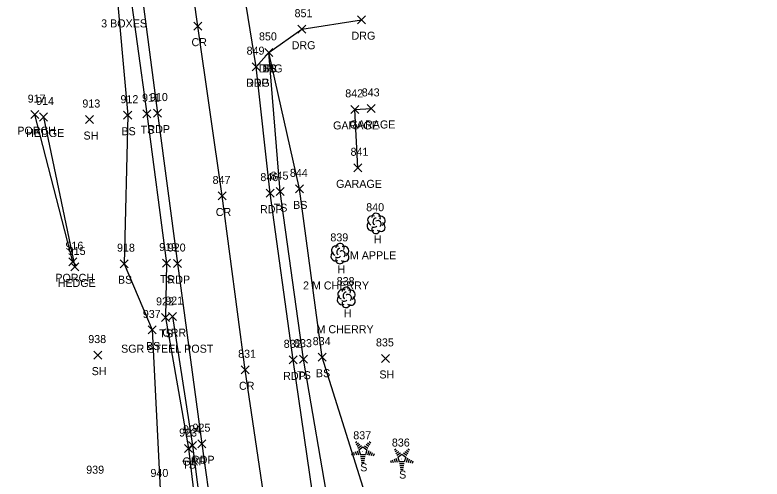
# Model space of a CAD drawing. Extents: x 1629176 to 1637209, y 606063 to 610167.
# Drawn here: x 1629888.9 to 1630075.4, y 607456.1 to 607571.9 of the extents above; entities that cross this region are included whole.
import ezdxf

# ---------------------------------------------------------------- set-up
doc = ezdxf.new("R2010")
doc.units = 0
for name, color, linetype in [('L_A', 7, 'Continuous'), ('L_C', 7, 'Continuous'), ('L_I', 7, 'Continuous'), ('L_TIC', 7, 'Continuous'), ('LAHR', 7, 'Continuous'), ('LBC', 7, 'Continuous'), ('LBF', 7, 'Continuous'), ('LELB', 7, 'Continuous'), ('LTC', 7, 'Continuous'), ('LTD', 7, 'Continuous'), ('P_A', 7, 'Continuous'), ('P_I', 7, 'Continuous'), ('P_TIC', 7, 'Continuous'), ('PET', 7, 'Continuous'), ('PRC', 7, 'Continuous'), ('R_A', 7, 'Continuous'), ('R_C', 7, 'Continuous'), ('R_I', 7, 'Continuous'), ('R_TIC', 7, 'Continuous'), ('RDG', 7, 'Continuous'), ('RGR', 7, 'Continuous')]:
    doc.layers.add(name, color=color, linetype=linetype)

msp = doc.modelspace()

# ---------------------------------------------------------------- linework, layer by layer
at = {"layer": 'L_TIC'}
for points in [[(1629951.27, 607561.54), (1629953.27, 607563.54)], [(1629953.27, 607561.54), (1629951.27, 607563.54)], [(1629951.27, 607561.54), (1629953.27, 607563.54)], [(1629953.27, 607561.54), (1629951.27, 607563.54)], [(1629976.84, 607547.56), (1629978.84, 607549.56)], [(1629978.84, 607547.56), (1629976.84, 607549.56)], [(1629892.84, 607546.01), (1629894.84, 607548.01)], [(1629894.84, 607546.01), (1629892.84, 607548.01)], [(1629916.02, 607545.87), (1629918.02, 607547.87)], [(1629918.02, 607545.87), (1629916.02, 607547.87)], [(1629920.84, 607546.23), (1629922.84, 607548.23)], [(1629922.84, 607546.23), (1629920.84, 607548.23)], [(1629972.72, 607547.32), (1629974.72, 607549.32)], [(1629974.72, 607547.32), (1629972.72, 607549.32)], [(1629894.96, 607545.42), (1629896.96, 607547.42)], [(1629896.96, 607545.42), (1629894.96, 607547.42)], [(1629906.5, 607544.79), (1629908.5, 607546.79)], [(1629908.5, 607544.79), (1629906.5, 607546.79)], [(1629973.47, 607532.74), (1629975.47, 607534.74)], [(1629975.47, 607532.74), (1629973.47, 607534.74)], [(1629958.9, 607527.48), (1629960.9, 607529.48)], [(1629960.9, 607527.48), (1629958.9, 607529.48)], [(1629954.08, 607526.79), (1629956.08, 607528.79)], [(1629956.08, 607526.79), (1629954.08, 607528.79)], [(1629902.34, 607509.29), (1629904.34, 607511.29)], [(1629904.34, 607509.29), (1629902.34, 607511.29)], [(1629915.16, 607508.81), (1629917.16, 607510.81)], [(1629917.16, 607508.81), (1629915.16, 607510.81)], [(1629925.69, 607508.97), (1629927.69, 607510.97)], [(1629927.69, 607508.97), (1629925.69, 607510.97)], [(1629902.84, 607508), (1629904.84, 607510)], [(1629904.84, 607508), (1629902.84, 607510)], [(1629925.47, 607495.41), (1629927.47, 607497.41)], [(1629927.47, 607495.41), (1629925.47, 607497.41)], [(1629922.16, 607492.27), (1629924.16, 607494.27)], [(1629924.16, 607492.27), (1629922.16, 607494.27)], [(1629908.54, 607486), (1629910.54, 607488)], [(1629910.54, 607486), (1629908.54, 607488)], [(1629959.93, 607484.98), (1629961.93, 607486.98)], [(1629961.93, 607484.98), (1629959.93, 607486.98)], [(1629964.59, 607485.49), (1629966.59, 607487.49)], [(1629966.59, 607485.49), (1629964.59, 607487.49)], [(1629980.39, 607485.17), (1629982.39, 607487.17)], [(1629982.39, 607485.17), (1629980.39, 607487.17)], [(1629931.23, 607462.67), (1629933.23, 607464.67)], [(1629933.23, 607462.67), (1629931.23, 607464.67)]]:
    msp.add_lwpolyline(points, dxfattribs=at)
at = {"layer": 'LAHR'}
msp.add_lwpolyline([(1629895.96, 607546.42), (1629903.84, 607509)], dxfattribs=at)
at = {"layer": 'LBC'}
msp.add_lwpolyline([(1629974.47, 607533.74), (1629973.72, 607548.32), (1629977.84, 607548.56)], dxfattribs=at)
at = {"layer": 'LBF'}
msp.add_lwpolyline([(1629903.34, 607510.29), (1629893.84, 607547.01)], dxfattribs=at)
at = {"layer": 'LELB'}
for points in [[(1629901.85, 607620.62), (1629912.64, 607607.29), (1629916.95, 607582.23), (1629921.84, 607547.23), (1629926.69, 607509.97), (1629926.47, 607496.41), (1629932.23, 607463.67), (1629936.65, 607426.68), (1629941.88, 607383.65), (1629948.66, 607331.72), (1629951.48, 607294.54)], [(1629872.74, 607605.4), (1629887.91, 607617.06), (1629901.2, 607617.32), (1629908.5, 607605.8), (1629913.9, 607581.78), (1629917.02, 607546.87), (1629916.16, 607509.81), (1629923.16, 607493.27), (1629925.16, 607453.58), (1629924.47, 607424.14), (1629903.61, 607389.66), (1629905.12, 607348.76), (1629905.7, 607299.56), (1629903.23, 607230.04), (1629906.81, 607190.46), (1629918.09, 607128.12), (1629917.39, 607086.84), (1629912.31, 607067.56), (1629894.57, 607057.72), (1629861.26, 607071.43), (1629823.99, 607082.84), (1629794.36, 607095.25), (1629802.79, 607128.03), (1629840.82, 607119.34)], [(1630084.2, 606935.53), (1630049.16, 606947.36), (1630020.53, 606959.33), (1630006.71, 606971.89), (1629998.15, 606985.2), (1629997.66, 607001.36), (1630003.56, 607031.17), (1630013.65, 607060.81), (1630014.9, 607093.95), (1630014.94, 607124.25), (1630010.97, 607149.73), (1630004.22, 607196.84), (1629997.94, 607243.02), (1629990.5, 607295.3), (1629983.84, 607333.53), (1629977.49, 607374.66), (1629974.09, 607413.89), (1629967.52, 607447.68), (1629960.93, 607485.98), (1629955.08, 607527.79), (1629952.27, 607562.54)], [(1630002.18, 607371.16), (1629996.83, 607417.59), (1629977.69, 607448.13), (1629965.59, 607486.49), (1629959.9, 607528.48), (1629952.27, 607562.54)]]:
    msp.add_lwpolyline(points, dxfattribs=at)
at = {"layer": 'LTC'}
for p, q in [((1629973.91, 607465.2), (1629974.27, 607465.46)), ((1629974.12, 607464.73), (1629974.65, 607465.12)), ((1629974.33, 607464.27), (1629975.04, 607464.78)), ((1629974.54, 607463.8), (1629975.42, 607464.44)), ((1629974.77, 607463.35), (1629975.78, 607464.08)), ((1629975.78, 607464.08), (1629976.78, 607463.36)), ((1629976.2, 607464.39), (1629977.01, 607463.81)), ((1629976.57, 607464.74), (1629977.25, 607464.25)), ((1629976.94, 607465.09), (1629977.49, 607464.69)), ((1629977.31, 607465.44), (1629977.73, 607465.14)), ((1629972.95, 607462.48), (1629973.1, 607462.01)), ((1629973.4, 607462.7), (1629973.61, 607462.04)), ((1629973.86, 607462.91), (1629974.13, 607462.08)), ((1629974.31, 607463.13), (1629974.64, 607462.11)), ((1629974.77, 607463.35), (1629975.15, 607462.15)), ((1629976.38, 607462.15), (1629975.15, 607462.15)), ((1629976.78, 607463.36), (1629976.38, 607462.15)), ((1629977.21, 607463.09), (1629976.88, 607462.05)), ((1629977.66, 607462.84), (1629977.37, 607461.95)), ((1629978.1, 607462.59), (1629977.87, 607461.86)), ((1629978.55, 607462.34), (1629978.36, 607461.76)), ((1629983.62, 607463.38), (1629983.97, 607463.64)), ((1629983.83, 607462.92), (1629984.35, 607463.3)), ((1629984.03, 607462.45), (1629984.74, 607462.96)), ((1629984.24, 607461.99), (1629985.12, 607462.63)), ((1629984.47, 607461.53), (1629985.48, 607462.27)), ((1629985.48, 607462.27), (1629986.48, 607461.54)), ((1629985.9, 607462.58), (1629986.71, 607461.99)), ((1629986.27, 607462.93), (1629986.95, 607462.43)), ((1629986.64, 607463.28), (1629987.19, 607462.88)), ((1629987.01, 607463.63), (1629987.43, 607463.32)), ((1629976.35, 607461.65), (1629975.2, 607461.65)), ((1629976.26, 607461.15), (1629975.27, 607461.15)), ((1629976.18, 607460.65), (1629975.35, 607460.65)), ((1629976.09, 607460.15), (1629975.42, 607460.15)), ((1629982.65, 607460.66), (1629982.8, 607460.2)), ((1629983.1, 607460.88), (1629983.32, 607460.23)), ((1629983.56, 607461.1), (1629983.83, 607460.26)), ((1629984.01, 607461.31), (1629984.35, 607460.29)), ((1629984.47, 607461.53), (1629984.86, 607460.34)), ((1629986.09, 607460.34), (1629984.86, 607460.34)), ((1629986.48, 607461.54), (1629986.09, 607460.34)), ((1629986.92, 607461.27), (1629986.58, 607460.23)), ((1629987.36, 607461.02), (1629987.07, 607460.14)), ((1629987.8, 607460.77), (1629987.57, 607460.04)), ((1629988.25, 607460.52), (1629988.06, 607459.95)), ((1629986.05, 607459.84), (1629984.9, 607459.84)), ((1629985.96, 607459.34), (1629984.98, 607459.34)), ((1629985.88, 607458.84), (1629985.05, 607458.84)), ((1629985.8, 607458.34), (1629985.12, 607458.34))]:
    msp.add_line(p, q, dxfattribs=at)
at = {"layer": 'LTD'}
for p, q in [((1629979.03, 607519.91), (1629979.03, 607519.91)), ((1629979.03, 607519.91), (1629979.03, 607519.91)), ((1629970.01, 607512.38), (1629970.01, 607512.38)), ((1629970.01, 607512.38), (1629970.01, 607512.38)), ((1629971.58, 607501.46), (1629971.58, 607501.46)), ((1629971.58, 607501.46), (1629971.58, 607501.46))]:
    msp.add_line(p, q, dxfattribs=at)
for centre in [(1629979.08, 607521.34), (1629970.05, 607513.81), (1629971.63, 607502.9)]:
    msp.add_arc(centre, 1.05, 335.5272, 180.9563, dxfattribs=at)
for centre, major_axis, ratio, start_param, end_param in [((1629978.24, 607520.58), (1.21, -0.51), 0.895232, 1.570796, 4.712389), ((1629980.08, 607520.49), (-1.14, -0.48), 0.949671, 1.570796, 4.712389), ((1629977.95, 607519.2), (0.58, -1.04), 0.959034, 3.141593, 6.283185), ((1629978.83, 607520.37), (-0.208, -0.792), 0.645439, 3.141593, 6.283185), ((1629979.53, 607519.74), (-0.5, 0.667), 0.989748, 3.141593, 6.283185), ((1629980.03, 607519.08), (-1.09, 0.79), 0.841452, 1.570796, 4.712389), ((1629979.03, 607518.41), (0.26, 1.06), 0.942809, 1.570796, 4.712389), ((1629978.58, 607519.16), (-0.625, -0.083), 0.423636, 0, 3.141593), ((1629969.22, 607513.05), (1.21, -0.51), 0.895232, 1.570796, 4.712389), ((1629971.05, 607512.96), (-1.14, -0.48), 0.949671, 1.570796, 4.712389), ((1629968.92, 607511.67), (0.58, -1.04), 0.959034, 3.141593, 6.283185), ((1629969.8, 607512.84), (-0.208, -0.792), 0.645439, 3.141593, 6.283185), ((1629970.51, 607512.21), (-0.5, 0.667), 0.989748, 3.141593, 6.283185), ((1629971.01, 607511.55), (-1.09, 0.79), 0.841452, 1.570796, 4.712389), ((1629970.01, 607510.88), (0.26, 1.06), 0.942809, 1.570796, 4.712389), ((1629969.55, 607511.63), (-0.625, -0.083), 0.423636, 0, 3.141593), ((1629970.79, 607502.13), (1.21, -0.51), 0.895232, 1.570796, 4.712389), ((1629972.62, 607502.05), (-1.14, -0.48), 0.949671, 1.570796, 4.712389), ((1629970.5, 607500.76), (0.58, -1.04), 0.959034, 3.141593, 6.283185), ((1629971.37, 607501.92), (-0.208, -0.792), 0.645439, 3.141593, 6.283185), ((1629972.08, 607501.3), (-0.5, 0.667), 0.989748, 3.141593, 6.283185), ((1629972.58, 607500.63), (-1.09, 0.79), 0.841452, 1.570796, 4.712389), ((1629971.58, 607499.96), (0.26, 1.06), 0.942809, 1.570796, 4.712389), ((1629971.12, 607500.71), (-0.625, -0.083), 0.423636, 0, 3.141593)]:
    msp.add_ellipse(centre, major_axis=major_axis, ratio=ratio, start_param=start_param, end_param=end_param, dxfattribs=at)
at = {"layer": 'P_TIC'}
for points in [[(1629933.53, 607568.1), (1629935.53, 607570.1)], [(1629935.53, 607568.1), (1629933.53, 607570.1)], [(1629948.09, 607557.98), (1629950.09, 607559.98)], [(1629950.09, 607557.98), (1629948.09, 607559.98)], [(1629923.47, 607546.4), (1629925.47, 607548.4)], [(1629925.47, 607546.4), (1629923.47, 607548.4)], [(1629939.59, 607525.71), (1629941.59, 607527.71)], [(1629941.59, 607525.71), (1629939.59, 607527.71)], [(1629951.57, 607526.42), (1629953.57, 607528.42)], [(1629953.57, 607526.42), (1629951.57, 607528.42)], [(1629928.48, 607508.85), (1629930.48, 607510.85)], [(1629930.48, 607508.85), (1629928.48, 607510.85)], [(1629957.35, 607484.82), (1629959.35, 607486.82)], [(1629959.35, 607484.82), (1629957.35, 607486.82)], [(1629945.39, 607482.34), (1629947.39, 607484.34)], [(1629947.39, 607482.34), (1629945.39, 607484.34)], [(1629934.58, 607463.89), (1629936.58, 607465.89)], [(1629936.58, 607463.89), (1629934.58, 607465.89)]]:
    msp.add_lwpolyline(points, dxfattribs=at)
at = {"layer": 'PET'}
for points in [[(1629979.67, 607327.82), (1629973.81, 607373.57), (1629968.79, 607410.79), (1629963.89, 607447.44), (1629958.35, 607485.82), (1629952.57, 607527.42), (1629949.09, 607558.98), (1629944.71, 607586.25), (1629940.16, 607615.76), (1629934.55, 607655.5), (1629928.02, 607704.49)], [(1629903.84, 607700.62), (1629910.61, 607651.05), (1629916.36, 607610.75), (1629919.9, 607582.29), (1629924.47, 607547.4), (1629929.48, 607509.85), (1629935.58, 607464.89), (1629940.69, 607427.92), (1629946.3, 607384.48), (1629952.98, 607332.78)]]:
    msp.add_lwpolyline(points, dxfattribs=at)
at = {"layer": 'PRC'}
msp.add_lwpolyline([(1629963.88, 606969.73), (1629972.76, 606997.52), (1629981.25, 607028.09), (1629988.12, 607066.47), (1629990.62, 607100.29), (1629990.61, 607124.69), (1629989.69, 607149.78), (1629986.77, 607182.68), (1629981.28, 607228.24), (1629975.13, 607276.5), (1629968.07, 607326.63), (1629961.78, 607372.25), (1629956.91, 607408.66), (1629951.88, 607446.34), (1629946.39, 607483.34), (1629940.59, 607526.71), (1629934.53, 607569.1), (1629928.23, 607613.94), (1629922.81, 607653.99), (1629916.48, 607702.82)], dxfattribs=at)
at = {"layer": 'R_TIC'}
for points in [[(1629974.44, 607569.71), (1629976.44, 607571.71)], [(1629976.44, 607569.71), (1629974.44, 607571.71)], [(1629959.49, 607567.33), (1629961.49, 607569.33)], [(1629961.49, 607567.33), (1629959.49, 607569.33)], [(1629951.27, 607561.54), (1629953.27, 607563.54)], [(1629953.27, 607561.54), (1629951.27, 607563.54)], [(1629948.09, 607557.98), (1629950.09, 607559.98)], [(1629950.09, 607557.98), (1629948.09, 607559.98)], [(1629927.19, 607495.6), (1629929.19, 607497.6)], [(1629929.19, 607495.6), (1629927.19, 607497.6)], [(1629932.22, 607463.46), (1629934.22, 607465.46)], [(1629934.22, 607463.46), (1629932.22, 607465.46)]]:
    msp.add_lwpolyline(points, dxfattribs=at)
at = {"layer": 'RDG'}
msp.add_lwpolyline([(1629949.09, 607558.98), (1629952.27, 607562.54), (1629960.49, 607568.33), (1629975.44, 607570.71)], dxfattribs=at)
at = {"layer": 'RGR'}
msp.add_lwpolyline([(1629928.19, 607496.6), (1629933.22, 607464.46), (1629937.95, 607427.21), (1629943.69, 607384.05), (1629950.32, 607332.08)], dxfattribs=at)

# ---------------------------------------------------------------- texts
at = {"layer": 'L_A'}
for s, p in [('TS', (1629950.68, 607557.54)), ('BS', (1629950.71, 607557.54)), ('PORCH', (1629889.46, 607542.01)), ('TS', (1629920.25, 607542.23)), ('GARAGE', (1629968.32, 607543.32)), ('GARAGE', (1629972.44, 607543.56)), ('HEDGE', (1629891.67, 607541.42)), ('SH', (1629905.99, 607540.79)), ('BS', (1629915.46, 607541.87)), ('GARAGE', (1629969.07, 607528.74)), ('BS', (1629958.34, 607523.48)), ('TS', (1629953.49, 607522.79)), ('H', (1629978.47, 607514.91)), ('H', (1629969.44, 607507.38)), ('PORCH', (1629898.96, 607505.29)), ('BS', (1629914.6, 607504.81)), ('TS', (1629925.1, 607504.97)), ('HEDGE', (1629899.54, 607504)), ('H', (1629971.01, 607496.46)), ('TS', (1629924.88, 607491.41)), ('BS', (1629921.6, 607488.27)), ('SH', (1629908.03, 607482)), ('TS', (1629959.34, 607480.98)), ('BS', (1629964.03, 607481.49)), ('SH', (1629979.88, 607481.17)), ('TS', (1629930.64, 607458.67)), ('S', (1629975.1, 607457.99)), ('S', (1629984.81, 607456.18))]:
    msp.add_text(s, height=2, dxfattribs=at).set_placement(p)
at = {"layer": 'L_C'}
for s, p in [('3 BOXES', (1629910.4, 607568.78)), ('M APPLE', (1629972.51, 607510.91)), ('2 M CHERRY', (1629960.81, 607503.38)), ('M CHERRY', (1629964.18, 607492.46))]:
    msp.add_text(s, height=2, dxfattribs=at).set_placement(p)
at = {"layer": 'L_I'}
for s, p in [('850', (1629949.82, 607565.54)), ('850', (1629949.82, 607565.54)), ('842', (1629971.36, 607551.32)), ('843', (1629975.48, 607551.56)), ('917', (1629892.05, 607550.01)), ('914', (1629894.17, 607549.42)), ('912', (1629915.22, 607549.87)), ('911', (1629920.61, 607550.23)), ('913', (1629905.71, 607548.79)), ('841', (1629972.68, 607536.74)), ('845', (1629952.71, 607530.79)), ('844', (1629957.54, 607531.48)), ('840', (1629976.59, 607522.91)), ('839', (1629967.64, 607515.38)), ('916', (1629901.49, 607513.29)), ('918', (1629914.36, 607512.81)), ('919', (1629924.89, 607512.97)), ('915', (1629902.05, 607512)), ('838', (1629969.22, 607504.46)), ('922', (1629924.11, 607499.41)), ('937', (1629920.8, 607496.27)), ('938', (1629907.18, 607490)), ('833', (1629958.57, 607488.98)), ('834', (1629963.23, 607489.49)), ('835', (1629979.03, 607489.17)), ('923', (1629929.87, 607466.67)), ('837', (1629973.36, 607465.99)), ('836', (1629983, 607464.18)), ('939', (1629906.67, 607457.4)), ('940', (1629922.71, 607456.58))]:
    msp.add_text(s, height=2, dxfattribs=at).set_placement(p)
at = {"layer": 'LTC'}
for p in [(1629975.66, 607463.1), (1629985.36, 607461.28)]:
    msp.add_text('.', height=1.04, rotation=270, dxfattribs=at).set_placement(p)
at = {"layer": 'P_A'}
for s, p in [('CR', (1629932.96, 607564.1)), ('RDP', (1629946.58, 607553.98)), ('RDP', (1629921.96, 607542.4)), ('CR', (1629939.02, 607521.71)), ('RDP', (1629950.06, 607522.42)), ('RDP', (1629926.97, 607504.85)), ('RDP', (1629955.84, 607480.82)), ('CR', (1629944.82, 607478.34)), ('RDP', (1629933.07, 607459.89))]:
    msp.add_text(s, height=2, dxfattribs=at).set_placement(p)
at = {"layer": 'P_I'}
for s, p in [('849', (1629946.72, 607561.98)), ('910', (1629922.59, 607550.4)), ('847', (1629938.23, 607529.71)), ('846', (1629950.16, 607530.42)), ('920', (1629927.03, 607512.85)), ('832', (1629955.99, 607488.82)), ('831', (1629944.6, 607486.34)), ('925', (1629933.22, 607467.89))]:
    msp.add_text(s, height=2, dxfattribs=at).set_placement(p)
at = {"layer": 'R_A'}
for s, p in [('DRG', (1629972.92, 607565.71)), ('DRG', (1629957.98, 607563.33)), ('DRG', (1629949.76, 607557.54)), ('DRG', (1629946.58, 607553.98)), ('GRR', (1629925.68, 607491.6)), ('GRR', (1629930.71, 607459.46))]:
    msp.add_text(s, height=2, dxfattribs=at).set_placement(p)
at = {"layer": 'R_C'}
msp.add_text('SGR STEEL POST', height=2, dxfattribs=at).set_placement((1629915.38, 607487.6))
at = {"layer": 'R_I'}
for s, p in [('851', (1629958.7, 607571.33)), ('850', (1629949.82, 607565.54)), ('849', (1629946.72, 607561.98)), ('921', (1629926.4, 607499.6)), ('924', (1629930.86, 607467.46))]:
    msp.add_text(s, height=2, dxfattribs=at).set_placement(p)

doc.saveas('drawing.dxf')
